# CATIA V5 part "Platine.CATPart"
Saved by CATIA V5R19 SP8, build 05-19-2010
Part number: Platine
Nomenclature: 51
Bounding box of the stored display mesh (mm): x -313 to 313, y -220 to 0, z 0 to 9
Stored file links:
  C:\Users\rphgr\Desktop\0_Tapis_TC520B_vitesse\Platine.CATPart
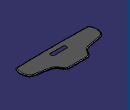
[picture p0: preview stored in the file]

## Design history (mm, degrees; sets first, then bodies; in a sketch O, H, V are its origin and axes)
Body1 (main body)
  AxisSystem1: origin (0, 0, 0), X (1, 0, 0), Y (0, 1, 0), Z (0, 0, 1)
  Sketch1 on XY plane of AxisSystem1, origin (0, 0, 0), H (1, 0, 0), V (0, 1, 0)
    line L1 (0, 0) -> (68, 0)
    arc A1 centre (68, -45) radius 45 from (68, 0) to (106.9711, -22.5) cw
    arc A2 centre (84.5402, -870.8698) radius 800 from (207.6601, -80.4006) to (271.6973, -93.0702) cw
    point P7 (84.5402, -870.8698)
    arc A3 centre (260, -141.6827) radius 50 from (271.6973, -93.0702) to (307.1154, -124.9453) cw
    point P9 (260, -141.6827)
    arc A4 centre (211, -159.0896) radius 102 from (307.1154, -124.9453) to (295.901, -215.6212) cw
    point P11 (211, -159.0896)
    arc A5 centre (0, 9780) radius 10000 from (295.901, -215.6212) to (0, -220) cw
    point P13 (0, 9780)
    point P14 (0, -220)
    line L2 (106.9711, -22.5) -> (116.9711, -39.8205)
    arc A6 centre (173.2628, -7.3205) radius 65 from (116.9711, -39.8205) to (157.8648, -70.4703) ccw
    arc A7 centre (300, 512.4513) radius 600 from (157.8648, -70.4703) to (207.6601, -80.4006) ccw
    point P17 (300, 512.4513)
    axis line L3 (0, 0) -> (0, -220)
    line L4 (0, 0) -> (0, -220)
    radius A7 = 600
    radius A2 = 800
    distance P14 L1 = 220
    length L1 = 68
    angle L2 L1 = 120
    radius A1 = 45
    length L2 = 20
    radius A6 = 65
    radius A5 = 10000
    radius A4 = 102
    radius A3 = 50
    distance P11 L3 = 211
    distance P9 L3 = 260
    distance P17 L3 = 300
    distance P7 L3 = 84.5402
    horizontal: L1 H
    tangency: A1 L1, A3 A2, A4 A3, L2 A1, A6 L2, A7 A6, A2 A7
    vertical: L3 V, L4 V
    coincidence: L3 P13, L3 V, L1 H
  Pad1: profile Sketch1, direction (0, 0, 1), length 9
  Chamfer1: length 6, angle 30, on edge [face of Pad1 from Sketch1.L1 | end face of Pad1]; edge [face of Pad1 from Sketch1.A5 | end face of Pad1]
  Mirror1: of the body so far, about face of Pad1 from Sketch1.L4
  Shell1: IntOffset 1, Face face of Pad1, ExtOffset 0
  Sketch2 on face of Pad1, origin (0, 0, 9), H (1, 0, 0), V (0, 1, 0)
    point P1 (0, -162)
    line L1 (58.5, -177) -> (-58.5, -177)
    line L2 (-58.5, -147) -> (58.5, -147)
    arc A1 centre (-23.5858, -162) radius 38 from (-58.5, -147) to (-58.5, -177) ccw
    arc A2 centre (23.5858, -162) radius 38 from (58.5, -147) to (58.5, -177) cw
    axis line L3 (23.5858, -162) -> (-23.5858, -162)
    distance L2 L1 = 30
    radius A1 = 38
    radius A2 = 38
    length L2 = 117
    distance L3 H = 162
    horizontal: L1 H, L2 H
    equidistance: L1 L2 P1
    midpoint: L3 P1
    coincidence: P1 V
    parallelism: L1 L3
  Pocket1: profile Sketch2, direction (0, 0, -1), through (limit type 3)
